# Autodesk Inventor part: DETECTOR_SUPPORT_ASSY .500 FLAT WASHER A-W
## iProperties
Shininess: 64.0
Length Units: 11272
Angle Units: 11279
Time Units: 11290
Mass Units: 11286
Length Display Precision: 3
Angle Display Precision: 2
Compacted: True
Part Number: DETECTOR_SUPPORT_ASSY .500 FLAT WASHER A-W
Document SubType Name: Modeling
Created: 2004-08
Designer: John Blackburn
Material: MILD_STEEL
Manufacturer: Standard
Standards Organization: Custom
Density: 0.0
Volumn: 0.0
Area: 0.0
PropertySet Name: Model Information
Control State: 0
Master: False
Checked Out: False
Author: John Blackburn
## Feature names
1. Base1
